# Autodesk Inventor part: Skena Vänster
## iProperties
Shininess: 64.0
Angle Display Precision: 2
Document Length Units: 11269
Document Angle Units: 11279
Document Time Units: 11290
Document Mass Units: 11283
Document Length Units Precision: 3
Document Angle Units Precision: 2
Created: 2001-12
Part Number: Skena Vänster
Material: S235JRG2
Document SubType Name: Modeling
Designer: Tobben
Density: 1 g/cm^3
Density: 0.0
Volumn: 0.0
Area: 0.0
PropertySet Name: Model Information
Control State: 0
Master: False
Checked Out: False
Author: Tobben
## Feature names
1. Extrusion1
2. Hole1
3. Rectangular Pattern1
4. Hole2
5. Extrusion3
6. Extrusion4
